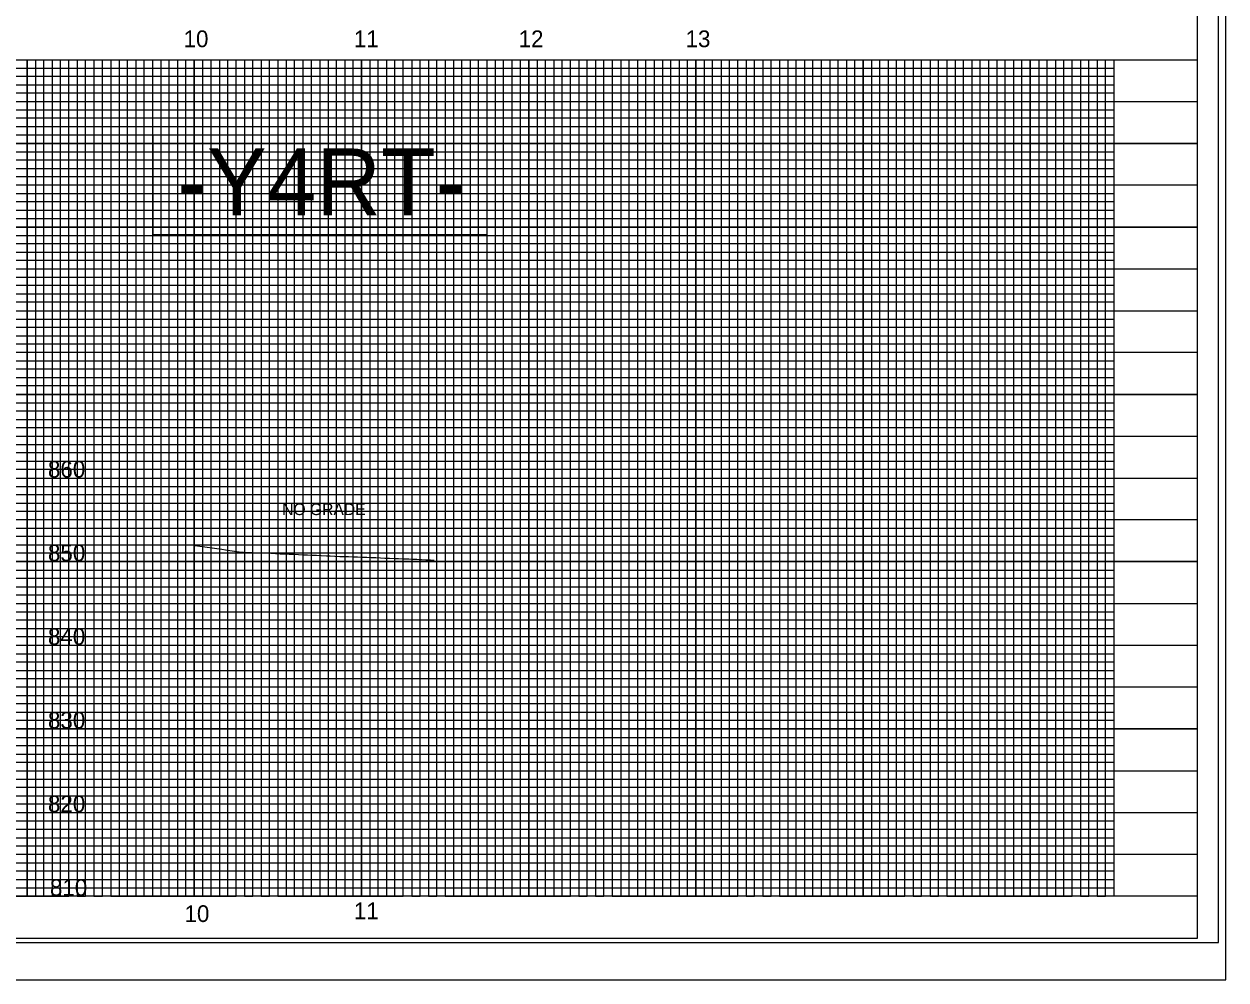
# Model space of a CAD drawing. Extents: x 570622 to 580296, y -55533 to -48575.
# Drawn here: x 571587 to 572306, y -54983 to -54411 of the extents above; entities that cross this region are included whole.
import ezdxf

# ---------------------------------------------------------------- set-up
doc = ezdxf.new("R2010")
doc.units = 0
for name, color, linetype in [('Default', 7, 'Continuous'), ('Exist Vertical Profile Ground Line', 7, 'Continuous'), ('Exist Vertical Profile Horizontal Axis Label Major', 7, 'Continuous'), ('Exist Vertical Profile Vertical Axis Label', 7, 'Continuous'), ('Prop Grid Mask', 7, 'Continuous'), ('Sheet Cutting Line CELL', 7, 'Continuous'), ('Sheet Data Field CELL', 7, 'Continuous'), ('Sheet DOT Grid CELL', 7, 'Continuous'), ('Sheet Layout Profile Border Port 2', 7, 'Continuous'), ('Sheet Plot Border Inside CELL', 7, 'Continuous'), ('Sheet Plot Border Outside CELL', 7, 'Continuous'), ('Sheet Profile CELL', 7, 'Continuous'), ('Sheet Profile Grid Major CELL', 7, 'Continuous'), ('Sheet Profile Grid Middle CELL', 7, 'Continuous'), ('Sheet Profile Grid Minor CELL', 7, 'Continuous')]:
    doc.layers.add(name, color=color, linetype=linetype)

msp = doc.modelspace()

# ---------------------------------------------------------------- linework, layer by layer
at = {"layer": 'Exist Vertical Profile Ground Line'}
msp.add_lwpolyline([(571688.69, -54723.01), (571690.64, -54723.29), (571705.14, -54725.29), (571707.29, -54725.59), (571710.02, -54725.97), (571712.75, -54726.34), (571715.47, -54726.72), (571718.2, -54727.08), (571720.93, -54727.16), (571723.65, -54727.25), (571726.38, -54727.33), (571729.11, -54727.42), (571731.83, -54727.5), (571734.56, -54727.58), (571737.28, -54727.73), (571738.05, -54727.77), (571738.54, -54727.82), (571739.09, -54727.88), (571740.01, -54727.92), (571742.74, -54728.04), (571745.46, -54728.16), (571748.19, -54728.28), (571750.92, -54728.4), (571753.64, -54728.52), (571756.37, -54728.64), (571759.1, -54728.76), (571761.82, -54728.88), (571764.55, -54729), (571767.79, -54729.16), (571770, -54729.26), (571772.73, -54729.38), (571775.64, -54729.51), (571778.18, -54729.6), (571780.91, -54729.7), (571783.63, -54729.8), (571786.36, -54729.89), (571789.09, -54729.99), (571791.81, -54730.09), (571794.54, -54730.19), (571796.01, -54730.24), (571796.74, -54730.28), (571797.27, -54730.3), (571799.99, -54730.41), (571802.72, -54730.52), (571805.45, -54730.62), (571808.17, -54730.73), (571810.9, -54730.84), (571813.63, -54730.94), (571816.35, -54731.05), (571817.09, -54731.09), (571819.08, -54731.17), (571821.8, -54731.28), (571823.27, -54731.34), (571824.53, -54731.4), (571827.26, -54731.53), (571829.98, -54731.66), (571832.18, -54731.77)], dxfattribs=at)
at = {"layer": 'Prop Grid Mask'}
msp.add_lwpolyline([(571664.14, -54477.48), (571863.6, -54477.48), (571863.6, -54537.34), (571664.14, -54537.34)], close=True, dxfattribs=at)
at = {"layer": 'Sheet Cutting Line CELL'}
msp.add_line((570621.69, -54982.69), (572305.69, -54982.69), dxfattribs=at)
at = {"layer": 'Sheet DOT Grid CELL'}
for p, q in [((570788.69, -54432.69), (572288.57, -54432.69)), ((571588.69, -54432.69), (571588.69, -54932.69)), ((571638.69, -54432.69), (571638.69, -54932.69)), ((571688.69, -54432.69), (571688.69, -54932.69)), ((571738.69, -54432.69), (571738.69, -54932.69)), ((571788.69, -54432.69), (571788.69, -54932.69)), ((571838.69, -54432.69), (571838.69, -54932.69)), ((571888.69, -54432.69), (571888.69, -54932.69)), ((571938.69, -54432.69), (571938.69, -54932.69)), ((571988.69, -54432.69), (571988.69, -54932.69)), ((572038.69, -54432.69), (572038.69, -54932.69)), ((572088.69, -54432.69), (572088.69, -54932.69)), ((572138.69, -54432.69), (572138.69, -54932.69)), ((572188.69, -54432.69), (572188.69, -54932.69)), ((572238.69, -54432.69), (572238.69, -54932.69)), ((570788.69, -54482.69), (572288.57, -54482.69)), ((570788.69, -54532.69), (572288.57, -54532.69)), ((570788.69, -54582.69), (572288.57, -54582.69)), ((570788.69, -54632.69), (572288.57, -54632.69)), ((570788.69, -54682.69), (572288.57, -54682.69)), ((570788.69, -54732.69), (572288.57, -54732.69)), ((570788.69, -54782.69), (572288.57, -54782.69)), ((570788.69, -54832.69), (572288.57, -54832.69)), ((570788.69, -54882.69), (572288.57, -54882.69))]:
    msp.add_line(p, q, dxfattribs=at)
at = {"layer": 'Sheet Layout Profile Border Port 2'}
msp.add_lwpolyline([(570838.69, -54432.69), (572238.69, -54432.69), (572238.69, -54932.69), (570838.69, -54932.69)], close=True, dxfattribs=at)
at = {"layer": 'Sheet Plot Border Inside CELL'}
msp.add_lwpolyline([(570634.69, -54960.24), (572301.19, -54960.24), (572301.19, -53905.14), (570634.69, -53905.14)], close=True, dxfattribs=at)
at = {"layer": 'Sheet Plot Border Outside CELL'}
msp.add_lwpolyline([(570621.69, -54982.69), (572305.69, -54982.69), (572305.69, -53882.69), (570621.69, -53882.69)], close=True, dxfattribs=at)
at = {"layer": 'Sheet Profile CELL'}
for p, q in [((570788.69, -54432.69), (572288.69, -54432.69)), ((572288.69, -54932.69), (570788.69, -54932.69)), ((570788.69, -54957.69), (572288.69, -54957.69))]:
    msp.add_line(p, q, dxfattribs=at)
msp.add_lwpolyline([(572288.69, -53907.69), (570788.69, -53907.69), (570788.69, -54957.69), (572288.69, -54957.69)], close=True, dxfattribs=at)
at = {"layer": 'Sheet Profile Grid Major CELL'}
for p, q in [((571588.69, -54432.69), (571638.69, -54432.69)), ((571688.69, -54432.69), (571738.69, -54432.69)), ((571788.69, -54432.69), (571838.69, -54432.69)), ((571888.69, -54432.69), (571938.69, -54432.69)), ((571988.69, -54432.69), (572038.69, -54432.69)), ((572088.69, -54432.69), (572138.69, -54432.69)), ((572188.69, -54432.69), (572238.69, -54432.69)), ((572188.69, -54932.69), (572188.69, -54932.69))]:
    msp.add_line(p, q, dxfattribs=at)
for points in [[(571538.69, -54932.69), (571588.69, -54932.69), (571588.69, -54432.69), (571638.69, -54432.69), (571638.69, -54932.69), (571688.69, -54932.69), (571688.69, -54432.69), (571738.69, -54432.69), (571738.69, -54932.69), (571788.69, -54932.69), (571788.69, -54432.69), (571838.69, -54432.69), (571838.69, -54932.69), (571888.69, -54932.69), (571888.69, -54432.69), (571938.69, -54432.69), (571938.69, -54932.69), (571988.69, -54932.69), (571988.69, -54432.69), (572038.69, -54432.69), (572038.69, -54932.69), (572088.69, -54932.69), (572088.69, -54432.69), (572138.69, -54432.69), (572138.69, -54932.69), (572188.69, -54932.69), (572188.69, -54932.69), (572188.69, -54432.69), (572238.69, -54432.69), (572238.69, -54932.69)], [(572288.69, -54482.69), (570788.69, -54482.69)], [(572288.69, -54532.69), (570788.69, -54532.69), (570788.69, -54582.69), (572288.69, -54582.69)], [(572288.69, -54632.69), (570788.69, -54632.69), (570788.69, -54682.69), (572288.69, -54682.69)], [(572288.69, -54732.69), (570788.69, -54732.69), (570788.69, -54782.69), (572288.69, -54782.69)], [(572288.69, -54832.69), (570788.69, -54832.69), (570788.69, -54832.69), (570788.69, -54882.69), (572288.69, -54882.69)], [(572288.69, -54932.69), (570788.69, -54932.69)]]:
    msp.add_lwpolyline(points, dxfattribs=at)
at = {"layer": 'Sheet Profile Grid Middle CELL'}
for points in [[(571563.69, -54932.69), (571613.69, -54932.69), (571613.69, -54432.69), (571663.69, -54432.69), (571663.69, -54932.69), (571713.69, -54932.69), (571713.69, -54432.69), (571763.69, -54432.69), (571763.69, -54932.69), (571813.69, -54932.69), (571813.69, -54432.69), (571863.69, -54432.69), (571863.69, -54932.69), (571913.69, -54932.69), (571913.69, -54432.69), (571963.69, -54432.69), (571963.69, -54932.69), (572013.69, -54932.69), (572013.69, -54432.69), (572063.69, -54432.69), (572063.69, -54932.69), (572113.69, -54932.69), (572113.69, -54432.69), (572163.69, -54432.69), (572163.69, -54932.69), (572213.69, -54932.69), (572213.69, -54432.69)], [(570788.69, -54457.69), (572288.69, -54457.69)], [(572288.69, -54507.69), (570788.69, -54507.69), (570788.69, -54557.69), (572288.69, -54557.69)], [(572288.69, -54607.69), (570788.69, -54607.69), (570788.69, -54657.69), (572288.69, -54657.69)], [(572288.69, -54707.69), (570788.69, -54707.69), (570788.69, -54757.69), (572288.69, -54757.69)], [(572288.69, -54807.69), (570788.69, -54807.69), (570788.69, -54857.69), (572288.69, -54857.69)], [(572288.69, -54907.69), (570788.69, -54907.69)]]:
    msp.add_lwpolyline(points, dxfattribs=at)
at = {"layer": 'Sheet Profile Grid Minor CELL'}
for p, q in [((570838.69, -54437.69), (572238.69, -54437.69)), ((572238.69, -54442.69), (570838.69, -54442.69)), ((570838.69, -54447.69), (572238.69, -54447.69)), ((572238.69, -54452.69), (570838.69, -54452.69)), ((570838.69, -54462.69), (572238.69, -54462.69)), ((572238.69, -54467.69), (570838.69, -54467.69)), ((570838.69, -54472.69), (572238.69, -54472.69)), ((572238.69, -54477.69), (570838.69, -54477.69)), ((570838.69, -54487.69), (572238.69, -54487.69)), ((572238.69, -54492.69), (570838.69, -54492.69)), ((570838.69, -54497.69), (572238.69, -54497.69)), ((572238.69, -54502.69), (570838.69, -54502.69)), ((570838.69, -54512.69), (572238.69, -54512.69)), ((572238.69, -54517.69), (570838.69, -54517.69)), ((570838.69, -54522.69), (572238.69, -54522.69)), ((572238.69, -54527.69), (570838.69, -54527.69)), ((570838.69, -54537.69), (572238.69, -54537.69)), ((572238.69, -54542.69), (570838.69, -54542.69)), ((570838.69, -54547.69), (572238.69, -54547.69)), ((572238.69, -54552.69), (570838.69, -54552.69)), ((570838.69, -54562.69), (572238.69, -54562.69)), ((572238.69, -54567.69), (570838.69, -54567.69)), ((570838.69, -54572.69), (572238.69, -54572.69)), ((572238.69, -54577.69), (570838.69, -54577.69)), ((570838.69, -54587.69), (572238.69, -54587.69)), ((572238.69, -54592.69), (570838.69, -54592.69)), ((570838.69, -54597.69), (572238.69, -54597.69)), ((572238.69, -54602.69), (570838.69, -54602.69)), ((570838.69, -54612.69), (572238.69, -54612.69)), ((572238.69, -54617.69), (570838.69, -54617.69)), ((570838.69, -54622.69), (572238.69, -54622.69)), ((572238.69, -54627.69), (570838.69, -54627.54)), ((570838.69, -54637.69), (572238.69, -54637.69)), ((572238.69, -54642.69), (570838.69, -54642.69)), ((570838.69, -54647.69), (572238.69, -54647.69)), ((572238.69, -54652.69), (570838.69, -54652.69)), ((570838.69, -54662.69), (572238.69, -54662.69)), ((572238.69, -54667.69), (570838.69, -54667.69)), ((570838.69, -54672.69), (572238.69, -54672.69)), ((572238.69, -54677.69), (570838.69, -54677.69)), ((570838.69, -54687.69), (572238.69, -54687.69)), ((572238.69, -54692.69), (570838.69, -54692.69)), ((570838.69, -54697.69), (572238.69, -54697.69)), ((572238.69, -54702.69), (570838.69, -54702.69)), ((570838.69, -54712.69), (572238.69, -54712.69)), ((572238.69, -54717.69), (570838.69, -54717.69)), ((570838.69, -54722.69), (572238.69, -54722.69)), ((572238.69, -54727.69), (570838.69, -54727.69)), ((570838.69, -54737.69), (572238.69, -54737.69)), ((572238.69, -54742.69), (570838.69, -54742.69)), ((570838.69, -54747.69), (572238.69, -54747.69)), ((572238.69, -54752.69), (570838.69, -54752.69)), ((570838.69, -54762.69), (572238.69, -54762.69)), ((572238.69, -54767.69), (570838.69, -54767.69)), ((570838.69, -54772.69), (572238.69, -54772.69)), ((572238.69, -54777.69), (570838.69, -54777.69)), ((570838.69, -54787.69), (572238.69, -54787.69)), ((572238.69, -54792.69), (570838.69, -54792.69)), ((570838.69, -54797.69), (572238.69, -54797.69)), ((572238.69, -54802.69), (570838.69, -54802.69)), ((570838.69, -54812.69), (572238.69, -54812.69)), ((572238.69, -54817.69), (570838.69, -54817.69)), ((570838.69, -54822.69), (572238.69, -54822.69)), ((572238.69, -54827.69), (570838.69, -54827.69)), ((570838.69, -54837.69), (572238.69, -54837.69)), ((572238.69, -54842.69), (570838.69, -54842.69)), ((570838.69, -54847.69), (572238.69, -54847.69)), ((572238.69, -54852.69), (570838.69, -54852.69)), ((570838.69, -54862.69), (572238.69, -54862.69)), ((572238.69, -54867.69), (570838.69, -54867.69)), ((570838.69, -54872.69), (572238.69, -54872.69)), ((572238.69, -54877.69), (570838.69, -54877.69)), ((570838.69, -54887.69), (572238.69, -54887.69)), ((572238.69, -54892.69), (570838.69, -54892.69)), ((570838.69, -54897.69), (572238.69, -54897.69)), ((572238.69, -54902.69), (570838.69, -54902.69)), ((570838.69, -54912.69), (572238.69, -54912.69)), ((572238.69, -54917.69), (570838.69, -54917.69)), ((570838.69, -54922.69), (572238.69, -54922.69)), ((570838.69, -54927.69), (572238.69, -54927.69)), ((572238.69, -54927.69), (572238.69, -54927.69))]:
    msp.add_line(p, q, dxfattribs=at)
for points in [[(571583.69, -54432.69), (571593.69, -54432.69), (571593.69, -54932.69), (571598.69, -54932.69), (571598.69, -54432.69), (571603.69, -54432.69), (571603.69, -54932.69), (571608.69, -54932.69), (571608.69, -54432.69), (571618.69, -54432.69), (571618.69, -54932.69), (571623.69, -54932.69), (571623.69, -54432.69), (571628.69, -54432.69), (571628.69, -54932.69), (571633.69, -54932.69), (571633.69, -54432.69), (571643.69, -54432.69), (571643.69, -54932.69), (571648.39, -54932.14), (571648.69, -54932.69), (571648.69, -54432.69), (571653.69, -54432.69), (571653.69, -54932.69), (571658.69, -54932.69), (571658.69, -54432.69), (571668.69, -54432.69), (571668.69, -54932.69), (571673.69, -54932.69)], [(571673.69, -54932.69), (571673.69, -54432.69), (571678.69, -54432.69), (571678.69, -54932.69), (571683.69, -54932.69), (571683.69, -54432.69), (571693.69, -54432.69), (571693.69, -54932.69), (571698.69, -54932.69), (571698.69, -54432.69), (571703.69, -54432.69), (571703.69, -54932.69), (571708.69, -54932.69), (571708.69, -54432.69), (571718.69, -54432.69), (571718.69, -54932.69), (571723.69, -54932.69), (571723.69, -54432.69), (571728.69, -54432.69), (571728.69, -54932.69), (571733.69, -54932.69), (571733.69, -54432.69), (571743.69, -54432.69), (571743.69, -54932.69), (571748.69, -54932.69), (571748.69, -54432.69), (571753.69, -54432.69), (571753.69, -54932.69), (571758.69, -54932.69), (571758.69, -54432.69), (571768.69, -54432.69), (571768.69, -54932.69), (571773.69, -54932.69), (571773.69, -54432.69), (571778.69, -54432.69), (571778.69, -54932.69), (571783.69, -54932.69), (571783.69, -54432.69), (571793.69, -54432.69), (571793.69, -54932.69), (571798.69, -54932.69), (571798.69, -54432.69), (571803.69, -54432.69), (571803.69, -54932.69), (571808.69, -54932.69), (571808.69, -54432.69), (571818.69, -54432.69), (571818.69, -54932.69), (571823.69, -54932.69), (571823.69, -54432.69), (571828.69, -54432.69), (571828.69, -54932.69), (571833.69, -54932.69), (571833.69, -54432.69), (571843.69, -54432.69), (571843.69, -54932.69), (571848.69, -54932.69), (571848.69, -54432.69), (571853.69, -54432.69), (571853.69, -54932.69), (571858.69, -54932.69), (571858.69, -54432.69), (571868.69, -54432.69), (571868.69, -54932.69), (571873.69, -54932.69), (571873.69, -54432.69), (571878.69, -54432.69), (571878.69, -54932.69), (571883.69, -54932.69), (571883.69, -54432.69), (571893.69, -54432.69), (571893.69, -54932.69), (571898.69, -54932.69), (571898.69, -54432.69), (571903.69, -54432.69), (571903.69, -54932.69), (571908.69, -54932.69), (571908.69, -54432.69), (571918.69, -54432.69), (571918.69, -54932.69), (571923.69, -54932.69), (571923.69, -54432.69), (571928.69, -54432.69), (571928.69, -54932.69), (571933.69, -54932.69), (571933.69, -54432.69), (571943.69, -54432.69), (571943.69, -54932.69), (571948.69, -54932.69), (571948.69, -54432.69), (571953.69, -54432.69), (571953.69, -54932.69), (571958.69, -54932.69), (571958.69, -54432.69), (571968.69, -54432.69), (571968.69, -54932.69), (571973.69, -54932.69), (571973.69, -54432.69), (571978.69, -54432.69), (571978.69, -54932.69)], [(571978.69, -54932.69), (571983.69, -54932.69), (571983.69, -54432.69), (571993.69, -54432.69), (571993.69, -54932.69), (571998.69, -54932.69), (571998.69, -54432.69), (572003.69, -54432.69), (572003.69, -54932.69), (572008.69, -54932.69), (572008.69, -54432.69), (572018.69, -54432.69), (572018.69, -54932.69), (572023.69, -54932.69), (572023.69, -54432.69), (572028.69, -54432.69), (572028.69, -54932.69), (572033.69, -54932.69), (572033.69, -54432.69), (572043.69, -54432.69), (572043.69, -54932.69), (572048.69, -54932.69), (572048.69, -54432.69), (572053.69, -54432.69), (572053.69, -54932.69), (572058.69, -54932.69), (572058.69, -54432.69), (572068.69, -54432.69), (572068.69, -54932.69), (572073.69, -54932.69), (572073.69, -54432.69), (572078.69, -54432.69), (572078.69, -54932.69), (572083.69, -54932.69), (572083.69, -54432.69), (572093.69, -54432.69), (572093.69, -54932.69), (572098.69, -54932.69), (572098.69, -54432.69), (572103.69, -54432.69), (572103.69, -54932.69), (572108.69, -54932.69), (572108.69, -54432.69), (572118.69, -54432.69), (572118.69, -54932.69), (572123.69, -54932.69), (572123.69, -54432.69), (572128.69, -54432.69), (572128.69, -54932.69), (572133.69, -54932.69), (572133.69, -54432.69), (572143.69, -54432.69), (572143.69, -54932.69), (572148.69, -54932.69), (572148.69, -54432.69), (572153.69, -54432.69), (572153.69, -54932.69), (572158.69, -54932.69), (572158.69, -54432.69), (572168.69, -54432.69), (572168.69, -54932.69), (572173.69, -54932.69), (572173.69, -54432.69), (572178.69, -54432.69), (572178.69, -54932.69), (572183.69, -54932.69), (572183.69, -54432.69), (572193.69, -54432.69), (572193.69, -54932.69), (572198.69, -54932.69), (572198.69, -54432.69), (572203.69, -54432.69), (572203.69, -54932.69), (572208.69, -54932.69), (572208.69, -54432.69), (572218.69, -54432.69), (572218.69, -54932.69), (572223.69, -54932.69), (572223.69, -54432.69), (572228.69, -54432.69), (572228.69, -54932.69), (572233.69, -54932.69), (572233.69, -54432.69), (572238.69, -54432.69)]]:
    msp.add_lwpolyline(points, dxfattribs=at)

# ---------------------------------------------------------------- texts
at = {"layer": 'Default'}
msp.add_text('NO GRADE', height=7, dxfattribs=at).set_placement((571741.23, -54704.87))
at = {"layer": 'Exist Vertical Profile Horizontal Axis Label Major'}
for s, p in [('10', (571682.27, -54425.19)), ('11', (571784.11, -54425.19)), ('12', (571882.66, -54425.19)), ('13', (571982.49, -54425.19)), ('10', (571682.83, -54948.06)), ('11', (571784.11, -54946.37))]:
    msp.add_text(s, height=10, dxfattribs=at).set_placement(p)
at = {"layer": 'Exist Vertical Profile Vertical Axis Label'}
for s, p in [('860', (571601.15, -54682.44)), ('850', (571601.15, -54732.44)), ('840', (571601.15, -54782.44)), ('830', (571601.15, -54832.44)), ('820', (571601.15, -54882.44)), ('810', (571602.35, -54932.44))]:
    msp.add_text(s, height=10, dxfattribs=at).set_placement(p)
at = {"layer": 'Sheet Data Field CELL'}
msp.add_text('-Y4RT-', height=40, dxfattribs=at).set_placement((571678.46, -54525.72))

doc.saveas('drawing.dxf')
